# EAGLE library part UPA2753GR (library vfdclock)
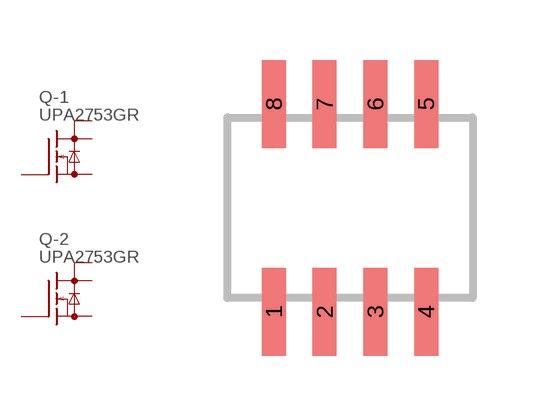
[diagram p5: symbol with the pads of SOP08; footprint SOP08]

Designator prefix Q; gates -1=MOSFET_N_D2 -2=MOSFET_N_D2

## UPA2753GR  [SOP08]
1  -1:S  pas
2  -1:G  pas
3  -2:S  pas
4  -2:G  pas
5  -2:D1  pas
6  -2:D2  pas
7  -1:D1  pas
8  -1:D2  pas

## Footprint SOP08 (pad centres in mm)
SMALL OUTLINE PACKAGE
smd 0.6 x 2.2: 1 -1.905,-2.6; 2 -0.635,-2.6; 3 0.635,-2.6; 4 1.905,-2.6; 5 1.905,2.6; 6 0.635,2.6; 7 -0.635,2.6; 8 -1.905,2.6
